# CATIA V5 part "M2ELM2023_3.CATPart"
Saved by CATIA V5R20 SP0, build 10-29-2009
Part number: Part1
Bounding box of the stored display mesh (mm): x -120 to 0, y -49.986 to 49.986, z -49.986 to 50
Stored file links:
  E:\0 Pedagogie\01 Hamma Lakhdar University\0Pedagogie\2023 2024\M2ELM CFAO\Travail a domicile 3\M2ELM2023_3.CATPart
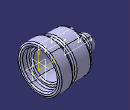
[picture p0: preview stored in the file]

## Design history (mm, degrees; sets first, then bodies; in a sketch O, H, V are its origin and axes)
Body1 (main body)
  Sketch1 on zx-plane, origin (0, 0, 0), H (-1, 0, 0), V (0, 0, 1)
    point P1 (0, 50)
    line L1 (0, 50) -> (30, 50)
    line L2 (30, 50) -> (30, 40)
    line L3 (30, 40) -> (40, 40)
    line L4 (40, 40) -> (40, 45)
    line L5 (40, 45) -> (75.8191, 45)
    line L6 (75.8191, 45) -> (90, 19.1236)
    line L7 (90, 19.1236) -> (90, 10)
    arc A1 centre (100, 0) radius 20 from (100, 20) to (120, 0) cw
    point P10 (120, 0)
    line L8 (90, 10) -> (95, 10)
    point P12 (95, 10)
    line L9 (95, 10) -> (100, 20)
    line L10 (0, 50) -> (0, 40)
    point P13 (0, 40)
    line L11 (0, 40) -> (15, 40)
    line L12 (15, 40) -> (15, 30)
    line L13 (15, 30) -> (60, 30)
    line L14 (60, 30) -> (60, 0)
    point P17 (60, 0)
    line L15 (60, 0) -> (120, 0)
    coincidence: P1 V, P10 H, P12 L6, P13 L3, P17 H
    horizontal: L1 H, L3 H, L5 H, L8 H, L11 H, L13 H, L15 H
    vertical: L2 V, L4 V, L7 V, L10 V, L12 V, L14 V
  Shaft1: profile Sketch1, axis Sketch1.L15, angle 360
  Fillet1: radius 3, on edge [face of Shaft1 from Sketch1.L9 | face of Shaft1 from Sketch1.A1]
  Fillet2: radius 3, on face of Shaft1 from Sketch1.L3; edge [face of Shaft1 from Sketch1.L1 | face of Shaft1 from Sketch1.L2]; edge [face of Shaft1 from Sketch1.L4 | face of Shaft1 from Sketch1.L5]; face of Shaft1 from Sketch1.L2
  Fillet3: radius 3, on edge [face of Shaft1 from Sketch1.L5 | face of Shaft1 from Sketch1.L6]; edge [face of Shaft1 from Sketch1.L10 | face of Shaft1 from Sketch1.L1]
  Fillet4: radius 3, on face of Shaft1 from Sketch1.L11; face of Shaft1 from Sketch1.L13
